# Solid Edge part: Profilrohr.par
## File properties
Username: bmolnar
Dokumentum tartalom típus: 0
Author: bmolnar
Last saved by: bmolnar
Revision: 83
Sűrűség: 0,000 kg/m^3
Pontosság: 0,990
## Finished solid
Body 1: solid body, 115 faces, 338 edges, 224 vertices.
  Faces by surface: cylinder 59, plane 56
  Edges by curve: line 220, circle 118
Bounding box of the edges (mm): 113.500 x 113.500 x 78.000, from (-56.75, -56.75, -61.5) to (56.75, 56.75, 16.5).
Cylindrical faces by radius (mm): R0.15 x24, R0.25 x24, R1 x4, R12.25 x4, R35 x2, R50 x1
Planar faces by outward normal: +x 13, +y 14, +z 1, -x 13, -y 14, -z 1
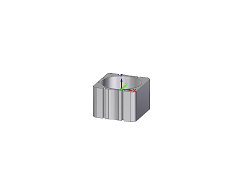
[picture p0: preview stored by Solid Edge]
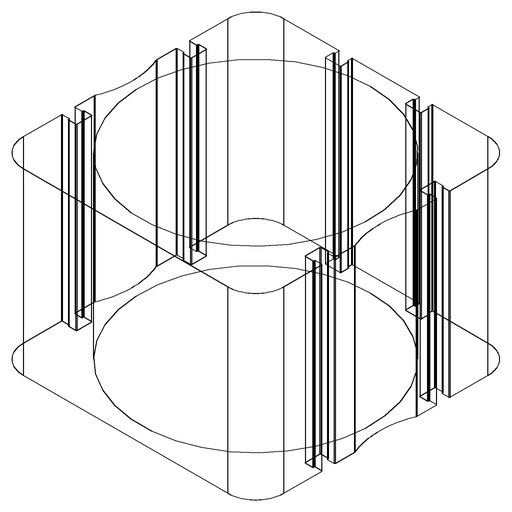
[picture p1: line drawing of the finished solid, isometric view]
